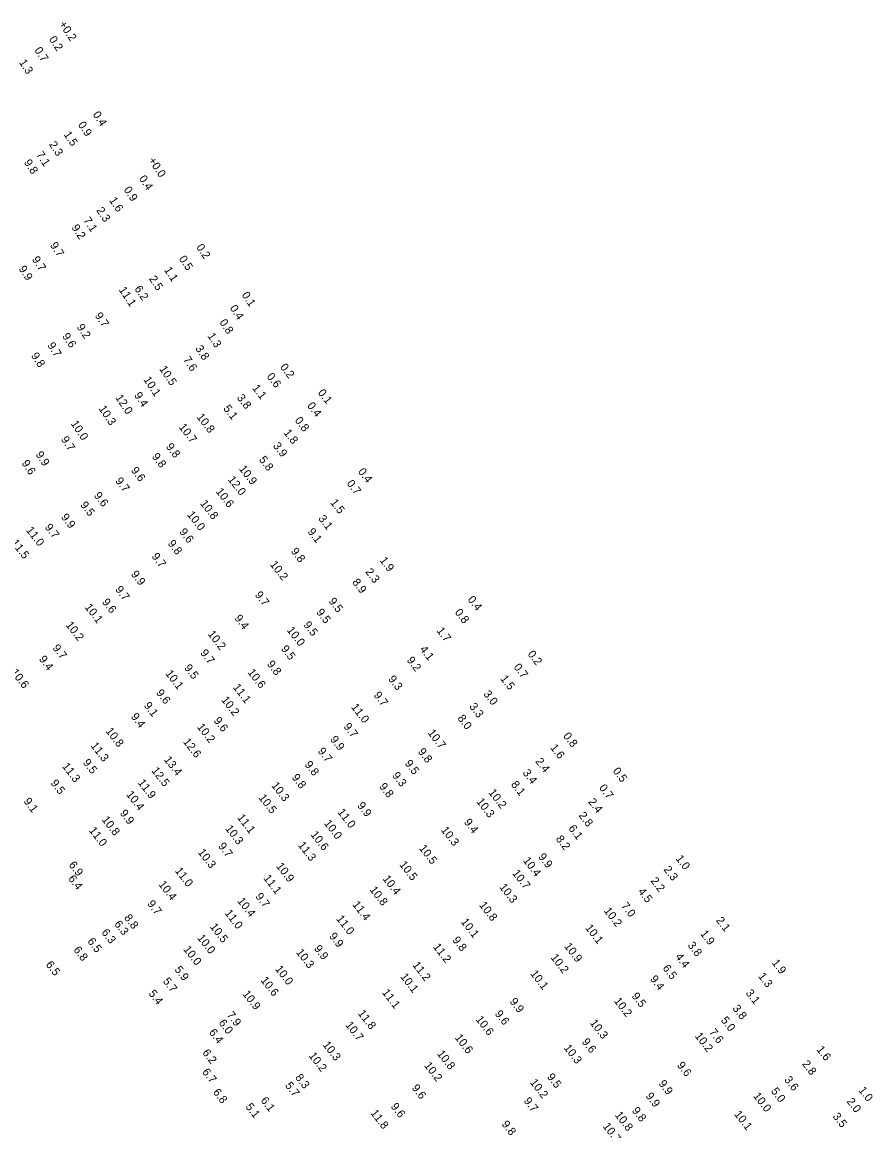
# Model space of a CAD drawing. Extents: x 815385 to 820851, y 582449 to 604245.
# Drawn here: x 817540 to 818064, y 595749 to 596432 of the extents above; entities that cross this region are included whole.
import ezdxf

# ---------------------------------------------------------------- set-up
doc = ezdxf.new("R2010")
doc.units = 0
doc.layers.add('V-TOPO-SOUN-020509C', color=7, linetype='Continuous')

msp = doc.modelspace()

# ---------------------------------------------------------------- texts
at = {"layer": 'V-TOPO-SOUN-020509C'}
for s, rotation, p in [('+0.2 ', 303.614, (817562.91, 596430.47)), ('0.2', 303.614, (817556.7, 596421.15)), ('0.7', 303.614, (817547.75, 596414.44)), ('1.3', 303.614, (817538.32, 596406.9)), ('0.4', 303.614, (817583.66, 596374.82)), ('0.9', 303.614, (817574.54, 596368.56)), ('1.5', 303.614, (817565.79, 596362.58)), ('7.1', 303.614, (817548.86, 596350.18)), ('2.3', 303.614, (817556.77, 596356.42)), ('9.8', 303.614, (817541.34, 596345.33)), ('+0.0 ', 303.614, (817617.87, 596346.58)), ('0.4', 303.614, (817612.11, 596335.45)), ('0.9', 303.614, (817602.73, 596328.57)), ('2.3', 303.614, (817585.88, 596315.88)), ('1.6', 303.614, (817593.81, 596322.07)), ('7.1', 303.614, (817577.87, 596309.71)), ('9.2', 303.614, (817570.61, 596305.26)), ('9.7', 303.614, (817557.39, 596294.36)), ('0.2', 303.614, (817647.43, 596293.2)), ('9.7', 303.614, (817546.24, 596285.64)), ('0.5', 303.614, (817636.73, 596286.01)), ('9.9', 303.614, (817538.05, 596279.86)), ('1.1', 303.614, (817627.61, 596279.18)), ('2.5', 303.614, (817618.31, 596273.73)), ('11.1 ', 303.614, (817599.73, 596266.92)), ('6.2', 303.614, (817609.35, 596267.59)), ('0.1', 303.614, (817675.41, 596263.79)), ('0.4', 303.614, (817668.05, 596255.7)), ('9.7', 303.614, (817584.95, 596251.1)), ('9.2', 303.614, (817573.8, 596244)), ('0.8', 303.614, (817661.69, 596246.95)), ('9.6', 303.614, (817564.85, 596238.41)), ('1.3', 303.614, (817654.33, 596238.55)), ('9.7', 303.614, (817555.77, 596232.72)), ('3.8', 303.614, (817646.83, 596230.85)), ('9.8', 303.614, (817545.68, 596226.4)), ('7.6', 303.614, (817639.35, 596224.01)), ('10.5 ', 303.614, (817624.67, 596218.27)), ('0.6', 307.782, (817690.72, 596213.47)), ('0.2', 307.782, (817698.95, 596219.25)), ('10.1 ', 303.614, (817614.91, 596211.68)), ('12.0 ', 303.614, (817597.6, 596200.6)), ('9.4', 303.614, (817609.18, 596202.03)), ('3.8', 307.782, (817672.37, 596200.4)), ('1.1', 307.782, (817681.81, 596206.37)), ('0.1', 307.782, (817722.22, 596203.5)), ('10.3 ', 303.614, (817587.33, 596193.82)), ('5.1', 307.782, (817664.02, 596193.81)), ('0.4', 307.782, (817715.64, 596195.5)), ('10.8 ', 307.782, (817647.6, 596188.57)), ('0.8', 307.782, (817708.04, 596186.44)), ('10.0 ', 303.614, (817570.19, 596184.59)), ('10.7 ', 307.782, (817636.63, 596182.34)), ('9.7', 303.614, (817564.12, 596174.89)), ('1.8', 307.782, (817701.19, 596178.85)), ('9.9', 303.614, (817548.46, 596165.61)), ('9.8', 307.782, (817628.64, 596170.3)), ('3.9', 307.782, (817694.6, 596170.83)), ('9.6', 303.614, (817539.85, 596160.25)), ('9.8', 307.782, (817620.03, 596164.19)), ('5.8', 307.782, (817685.98, 596162.31)), ('9.6', 307.782, (817607.12, 596155.7)), ('10.9 ', 307.782, (817673.69, 596156.68)), ('0.4', 307.782, (817746.95, 596154.93)), ('9.7', 307.782, (817597.47, 596149.21)), ('12.0 ', 307.782, (817666.83, 596150.1)), ('0.7', 307.782, (817740.02, 596147.64)), ('9.6', 307.782, (817584.31, 596140.21)), ('10.6 ', 307.782, (817659.4, 596142.71)), ('9.5', 307.782, (817575.98, 596134.41)), ('10.8 ', 307.782, (817649.77, 596135.33)), ('1.5', 307.782, (817729.92, 596135.91)), ('9.9', 307.782, (817564.09, 596126.91)), ('10.0 ', 307.782, (817641.72, 596128.47)), ('3.1', 307.782, (817722.55, 596126.03)), ('11.0 ', 307.782, (817542.62, 596118.9)), ('9.7', 307.782, (817554.07, 596120.68)), ('9.6', 307.782, (817636.94, 596117.91)), ('9.1', 307.782, (817715.92, 596117.97)), ('11.5 ', 307.782, (817533.38, 596111.09)), ('9.8', 307.782, (817629.82, 596110.69)), ('9.8', 307.782, (817705.6, 596105.92)), ('9.7', 307.782, (817619.89, 596102.76)), ('10.2 ', 307.782, (817692.75, 596097.84)), ('1.9', 307.782, (817760.34, 596100.32)), ('9.9', 307.782, (817607.19, 596091.79)), ('2.3', 307.782, (817751.46, 596093.29)), ('8.9', 307.782, (817743.37, 596086.88)), ('9.7', 307.782, (817597.47, 596082.43)), ('9.7', 307.782, (817683.45, 596079.08)), ('10.1 ', 307.782, (817578.69, 596071.49)), ('9.6', 307.782, (817589.31, 596074.66)), ('9.5', 307.782, (817728.83, 596075.13)), ('0.4', 307.782, (817814.49, 596076.24)), ('9.4', 307.782, (817670.89, 596064.71)), ('9.5', 307.782, (817721.28, 596068.38)), ('0.8', 307.782, (817806.54, 596068.33)), ('10.2 ', 307.782, (817567.02, 596060.54)), ('10.0 ', 307.782, (817703.18, 596057.35)), ('9.5', 307.782, (817713.38, 596060.61)), ('1.7', 307.782, (817795.37, 596057.03)), ('10.2 ', 307.782, (817654.45, 596054.98)), ('9.7', 307.782, (817558.84, 596046.4)), ('9.7', 307.782, (817649.84, 596043.34)), ('9.5', 307.782, (817699.53, 596045.89)), ('4.1', 307.782, (817784.96, 596045.61)), ('0.2', 307.782, (817851.42, 596042.64)), ('9.4', 307.782, (817550.51, 596039.49)), ('9.8', 307.782, (817690.88, 596036.47)), ('9.2', 307.782, (817777, 596038.88)), ('10.6 ', 307.782, (817533.2, 596031.37)), ('10.1 ', 307.782, (817628.35, 596030.69)), ('9.5', 307.782, (817639.92, 596034.14)), ('10.6 ', 307.782, (817679, 596031.4)), ('0.7', 307.782, (817842.81, 596034.6)), ('9.3', 307.782, (817765.56, 596027.29)), ('1.5', 307.782, (817834.62, 596027.48)), ('9.6', 307.782, (817622.63, 596018.78)), ('11.1 ', 307.782, (817669.96, 596022.18)), ('9.7', 307.782, (817756.59, 596017.37)), ('3.0', 307.782, (817824.2, 596018.1)), ('9.1', 307.782, (817615.07, 596011)), ('10.2 ', 307.782, (817662.79, 596014.45)), ('11.0 ', 307.782, (817742.72, 596010.02)), ('3.3', 307.782, (817815.5, 596010.38)), ('9.4', 307.782, (817607.13, 596004.12)), ('9.6', 307.782, (817658.08, 596001.68)), ('8.0', 307.782, (817808.24, 596003.09)), ('10.8 ', 307.782, (817591.57, 595995.25)), ('10.2 ', 307.782, (817647.85, 595997.78)), ('9.7', 307.782, (817738.05, 595998.05)), ('12.6 ', 307.782, (817639.24, 595988.67)), ('9.9', 307.782, (817729.84, 595990.14)), ('10.7 ', 307.782, (817789.92, 595994.15)), ('0.8', 307.782, (817873.32, 595992.2)), ('11.3 ', 307.782, (817582.35, 595986.23)), ('9.7', 307.782, (817722.19, 595982.9)), ('9.8', 307.782, (817783.85, 595982.57)), ('1.6', 307.782, (817865.33, 595985.05)), ('9.5', 307.782, (817577.52, 595975.87)), ('13.4 ', 307.782, (817627.49, 595977.65)), ('9.8', 307.782, (817714.07, 595974.63)), ('9.5', 307.782, (817775.77, 595975.37)), ('2.4', 307.782, (817856.19, 595976.59)), ('11.3 ', 307.782, (817564.8, 595973.54)), ('12.5 ', 307.782, (817619.79, 595970.92)), ('9.3', 307.782, (817768, 595967.91)), ('3.4', 307.782, (817848.37, 595969.55)), ('0.5', 307.782, (817903.82, 595970.65)), ('9.5', 307.782, (817557.7, 595963.19)), ('11.9 ', 307.782, (817611.4, 595963.48)), ('10.3 ', 307.782, (817693.61, 595961.76)), ('9.8', 307.782, (817706.2, 595966.72)), ('9.8', 307.782, (817760.01, 595961.14)), ('8.1', 307.782, (817841.2, 595962.38)), ('10.4 ', 307.782, (817604.23, 595956.26)), ('10.5 ', 307.782, (817685.78, 595954.26)), ('10.2 ', 307.782, (817827.32, 595957.4)), ('0.7', 307.782, (817895.41, 595960.28)), ('9.1', 307.782, (817541.05, 595951.99)), ('9.9', 307.782, (817746.49, 595949.38)), ('10.3 ', 307.782, (817819.89, 595951.83)), ('2.4', 307.782, (817888.74, 595951.72)), ('10.8 ', 307.782, (817589.2, 595940.75)), ('9.9', 307.782, (817600.31, 595944.69)), ('11.1 ', 307.782, (817672.58, 595942)), ('11.0 ', 307.782, (817734.37, 595945.33)), ('2.8', 307.782, (817882.81, 595943.29)), ('11.0 ', 307.782, (817581.31, 595934.08)), ('10.3 ', 307.782, (817665.23, 595935.21)), ('10.0 ', 307.782, (817726, 595938.47)), ('10.3 ', 307.782, (817798.06, 595934.35)), ('9.4', 307.782, (817812.2, 595939.14)), ('6.1', 307.782, (817876.55, 595935.31)), ('10.6 ', 307.782, (817717.79, 595931.53)), ('8.2', 307.782, (817868.77, 595928.85)), ('10.3 ', 307.782, (817648.37, 595920.6)), ('9.7', 307.782, (817660.88, 595924.4)), ('11.3 ', 307.782, (817710.03, 595925.02)), ('10.5 ', 307.782, (817784.56, 595923.1)), ('10.5 ', 307.782, (817772.44, 595913.1)), ('10.4 ', 307.782, (817848.57, 595915.58)), ('9.9', 307.782, (817857.94, 595917.84)), ('1.0', 307.782, (817942.59, 595916.76)), ('6.9', 307.782, (817568.84, 595912.85)), ('11.0 ', 307.782, (817634.24, 595909.24)), ('10.9 ', 307.782, (817696.56, 595912.08)), ('10.7 ', 307.782, (817841.95, 595907.77)), ('2.3', 307.782, (817935.14, 595910.05)), ('6.4', 307.782, (817568.52, 595904.42)), ('10.4 ', 307.782, (817624.15, 595900.92)), ('11.1 ', 307.782, (817688.76, 595904.7)), ('10.4 ', 307.782, (817762.17, 595904.33)), ('2.2', 307.782, (817927.1, 595903.1)), ('9.7', 307.782, (817683.78, 595893.44)), ('10.8 ', 307.782, (817754.14, 595897.6)), ('10.3 ', 307.782, (817834, 595899.24)), ('4.5', 307.782, (817919.35, 595896.49)), ('9.7', 307.782, (817617.2, 595888.98)), ('10.4 ', 307.782, (817672.67, 595890.65)), ('11.4 ', 307.782, (817743.53, 595888.49)), ('10.8 ', 307.782, (817821.6, 595888.12)), ('7.0', 307.782, (817909.02, 595887.62)), ('8.8', 307.782, (817602.9, 595880.31)), ('11.0 ', 307.782, (817664.87, 595883.23)), ('11.0 ', 307.782, (817733.58, 595879.72)), ('10.2 ', 307.782, (817898.37, 595884.62)), ('2.1', 307.782, (817967.44, 595878.71)), ('6.3', 307.782, (817596.85, 595876.49)), ('10.5 ', 307.782, (817655.81, 595874.82)), ('10.1 ', 307.782, (817810.36, 595877.84)), ('10.1 ', 307.782, (817886.9, 595874.1)), ('6.5', 307.782, (817580.32, 595865.81)), ('6.3', 307.782, (817589.03, 595871.28)), ('10.0 ', 307.782, (817647.98, 595867.95)), ('9.9', 307.782, (817729.2, 595868.99)), ('9.8', 307.782, (817805.1, 595866.62)), ('1.9', 307.782, (817957.74, 595870.48)), ('6.8', 307.782, (817571.76, 595860.58)), ('10.0 ', 307.782, (817639.43, 595860.9)), ('10.3 ', 307.782, (817708.84, 595859.06)), ('9.9', 307.782, (817719.9, 595861.36)), ('11.2 ', 307.782, (817793.21, 595862.44)), ('10.9 ', 307.782, (817873.94, 595862.78)), ('3.8', 307.782, (817949.94, 595863.4)), ('10.2 ', 307.782, (817865.59, 595855.89)), ('4.4', 307.782, (817942.29, 595856.34)), ('1.9', 307.782, (818001.79, 595852.57)), ('6.5', 307.782, (817554.68, 595851.53)), ('5.9', 307.782, (817633.99, 595848.44)), ('10.0 ', 307.782, (817695.91, 595848.77)), ('11.2 ', 307.782, (817780.52, 595851.23)), ('10.1 ', 307.782, (817853.09, 595845.92)), ('6.5', 307.782, (817934.54, 595849.31)), ('5.7', 307.782, (817626.79, 595841.27)), ('10.6 ', 307.782, (817687.02, 595841.89)), ('10.1 ', 307.782, (817773.05, 595844.06)), ('9.4', 307.782, (817926.79, 595842.68)), ('1.3', 307.782, (817993.38, 595844.33)), ('5.4', 307.782, (817618, 595833.72)), ('10.9 ', 307.782, (817675.85, 595833.45)), ('11.1 ', 307.782, (817761.78, 595834.3)), ('9.5', 307.782, (817915.51, 595832.09)), ('3.1', 307.782, (817985.71, 595834.02)), ('9.9', 307.782, (817840.34, 595828.77)), ('10.2 ', 307.782, (817904.56, 595829.12)), ('3.8', 307.782, (817977.57, 595824.58)), ('7.9', 307.782, (817666.16, 595820.45)), ('11.8 ', 307.782, (817746.88, 595821.47)), ('10.6 ', 307.782, (817819.43, 595817.77)), ('9.6', 307.782, (817831.21, 595821.21)), ('5.0', 307.782, (817970.43, 595817.28)), ('6.0', 307.782, (817661.14, 595815.62)), ('10.7 ', 307.782, (817739.21, 595814.34)), ('10.3 ', 307.782, (817889.77, 595815.6)), ('6.4', 307.782, (817655.2, 595809.8)), ('10.6 ', 307.782, (817806.61, 595806.53)), ('9.6', 307.782, (817884.78, 595803.97)), ('10.2 ', 307.782, (817954.41, 595807.52)), ('7.6', 307.782, (817963.17, 595809.91)), ('6.2', 307.782, (817651.11, 595797.27)), ('10.3 ', 307.782, (817725.23, 595802.15)), ('10.3 ', 307.782, (817873.71, 595800.24)), ('1.6', 307.782, (818029.33, 595799.25)), ('10.2 ', 307.782, (817716.64, 595795.44)), ('10.8 ', 307.782, (817795.66, 595796.65)), ('2.8', 307.782, (818020.42, 595790.38)), ('6.7', 307.782, (817651.01, 595785.42)), ('10.2 ', 307.782, (817787.69, 595789.38)), ('9.6', 307.782, (817943.44, 595789.52)), ('5.7', 307.782, (817702.06, 595777.07)), ('8.3', 307.782, (817708.29, 595782.02)), ('10.2 ', 307.782, (817852.9, 595778.99)), ('9.5', 307.782, (817863.34, 595782.39)), ('9.9', 307.782, (817932.04, 595778.24)), ('3.6', 307.782, (818009.47, 595780.65)), ('6.8', 307.782, (817657.65, 595772.93)), ('9.6', 307.782, (817780.06, 595775.59)), ('9.9', 307.782, (817924.09, 595770.59)), ('10.0 ', 307.782, (817990.34, 595770.6)), ('5.0', 307.782, (818001.29, 595773.58)), ('1.0', 307.782, (818055.19, 595774.16)), ('5.1', 307.782, (817677.72, 595764)), ('6.1', 307.782, (817686.98, 595767.89)), ('9.6', 307.782, (817767.15, 595764.16)), ('9.7', 307.782, (817849.03, 595767.62)), ('2.0', 307.782, (818047.89, 595767.3)), ('11.8 ', 307.782, (817754.64, 595760.14)), ('10.8 ', 307.782, (817905.15, 595758.91)), ('9.8', 307.782, (817915.64, 595761.66)), ('10.1 ', 307.782, (817978.58, 595759.44)), ('3.5', 307.782, (818039.25, 595758.1)), ('9.8', 307.782, (817835.41, 595753.27)), ('10.7 ', 307.782, (817897.73, 595751.99))]:
    msp.add_text(s, height=5, rotation=rotation, dxfattribs=at).set_placement(p)

doc.saveas('drawing.dxf')
